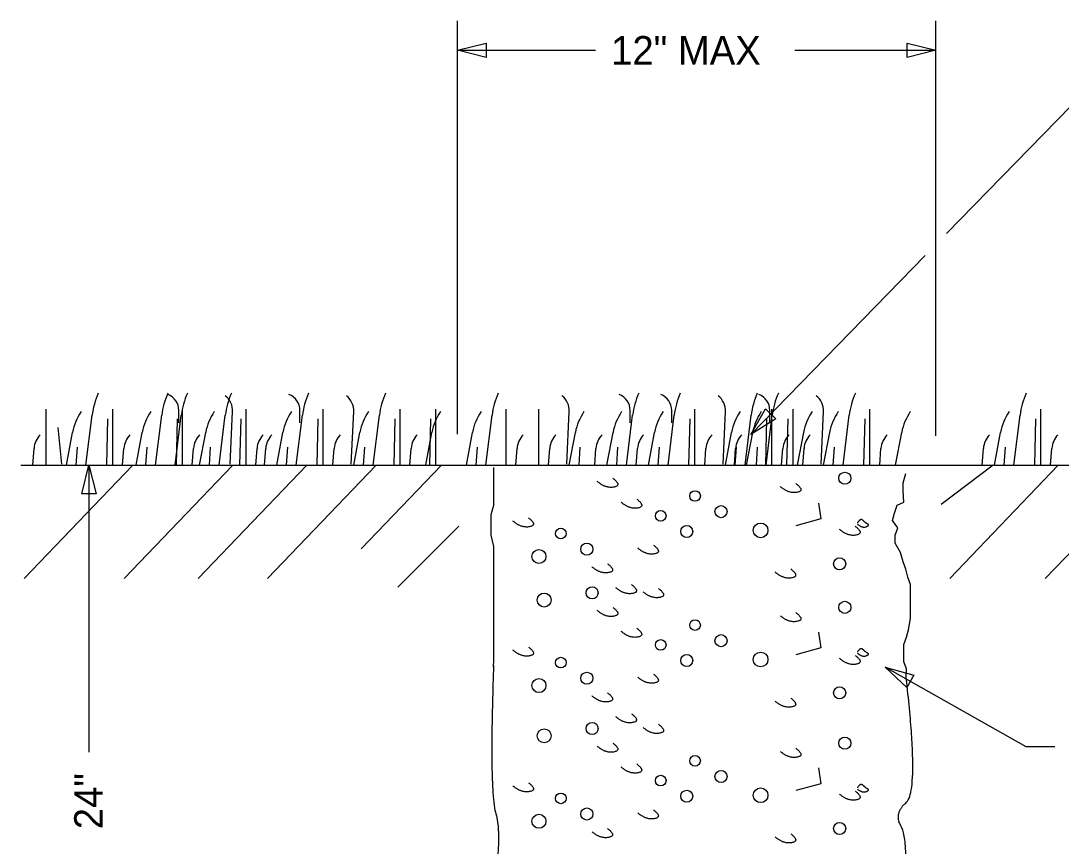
# Model space of a CAD drawing. Extents: x 10111 to 10157.2, y 10072.4 to 10116.1.
# Drawn here: x 10110.98 to 10135.23, y 10096.92 to 10116.14 of the extents above; entities that cross this region are included whole.
import ezdxf

# ---------------------------------------------------------------- set-up
doc = ezdxf.new("R2010")
doc.units = 0
for name, color, linetype in [('G-ANNO-TEXT', 7, 'Continuous'), ('G-DETL-LINE', 7, 'Continuous'), ('G-DETL-PATT', 7, 'Continuous')]:
    doc.layers.add(name, color=color, linetype=linetype)

msp = doc.modelspace()

# ---------------------------------------------------------------- linework, layer by layer
at = {"layer": 'G-ANNO-TEXT'}
for p, q in [((10121.155, 10106.519), (10121.155, 10116.144)), ((10132.304, 10106.479), (10132.304, 10116.144)), ((10121.155, 10115.459), (10124.375, 10115.459)), ((10129.02, 10115.459), (10132.304, 10115.459)), ((10135.967, 10114.69), (10132.554, 10111.19)), ((10132.054, 10110.677), (10127.992, 10106.511)), ((10112.564, 10105.794), (10112.564, 10099.107)), ((10134.41, 10099.234), (10131.128, 10101.086)), ((10135.076, 10099.234), (10134.41, 10099.234))]:
    msp.add_line(p, q, dxfattribs=at)
for points in [[(10121.822, 10115.292), (10121.155, 10115.459), (10121.822, 10115.626)], [(10131.637, 10115.626), (10132.304, 10115.459), (10131.637, 10115.292)], [(10128.577, 10106.872), (10127.992, 10106.511), (10128.339, 10107.105)], [(10112.398, 10105.127), (10112.564, 10105.794), (10112.731, 10105.127)], [(10131.627, 10100.613), (10131.128, 10101.086), (10131.79, 10100.904)]]:
    msp.add_lwpolyline(points, close=True, dxfattribs=at)
at = {"layer": 'G-DETL-LINE'}
msp.add_line((10110.977, 10105.793), (10143.768, 10105.793), dxfattribs=at)
for points in [[(10121.995, 10101.091), (10122.002, 10101.262), (10122.002, 10101.448), (10122.002, 10101.618), (10122.002, 10101.789), (10122.002, 10102.052), (10122.002, 10102.238), (10122.002, 10102.455), (10122.002, 10102.672), (10122.002, 10102.936), (10122.002, 10103.199), (10122.002, 10103.416), (10122.002, 10103.633), (10122.002, 10103.897), (10121.94, 10104.16), (10121.94, 10104.424), (10121.94, 10104.641), (10122.002, 10104.858), (10122.002, 10105.075), (10122.002, 10105.338), (10122.002, 10105.524), (10122.002, 10105.741)], [(10131.617, 10100.825), (10131.622, 10101.045), (10131.56, 10101.215), (10131.56, 10101.432), (10131.56, 10101.618), (10131.622, 10101.789), (10131.669, 10101.959), (10131.715, 10102.223), (10131.715, 10102.44), (10131.715, 10102.626), (10131.715, 10102.843), (10131.715, 10103.013), (10131.653, 10103.184), (10131.607, 10103.37), (10131.545, 10103.54), (10131.483, 10103.757), (10131.359, 10103.974), (10131.359, 10104.16), (10131.421, 10104.331), (10131.297, 10104.501), (10131.343, 10104.672), (10131.405, 10104.858), (10131.56, 10104.935), (10131.545, 10105.199), (10131.545, 10105.385), (10131.607, 10105.602)]]:
    msp.add_lwpolyline(points, dxfattribs=at)
msp.add_open_spline([(10121.996, 10101.13), (10121.895, 10098.19), (10122.199, 10097.176), (10121.794, 10094.642), (10122.401, 10092.412), (10122.3, 10091.095), (10122.806, 10090.284), (10122.098, 10088.865), (10122.604, 10085.52), (10125.541, 10086.027), (10127.768, 10085.115), (10129.49, 10086.027), (10130.908, 10086.331), (10131.718, 10088.358), (10131.212, 10092.514), (10131.718, 10096.973), (10131.313, 10097.683), (10131.92, 10098.19), (10131.617, 10100.825)], degree=2, dxfattribs=at)
at = {"layer": 'G-DETL-PATT'}
for p, q in [((10113.591, 10105.791), (10111.059, 10103.156)), ((10115.92, 10105.791), (10113.389, 10103.156)), ((10117.642, 10105.791), (10115.11, 10103.156)), ((10119.262, 10105.791), (10116.73, 10103.156)), ((10120.781, 10105.791), (10118.912, 10103.846)), ((10133.642, 10105.791), (10132.427, 10104.879)), ((10135.161, 10105.791), (10132.629, 10103.156)), ((10137.389, 10105.791), (10134.857, 10103.156)), ((10129.571, 10104.91), (10129.624, 10104.542)), ((10121.186, 10104.372), (10119.768, 10102.953)), ((10129.624, 10104.542), (10129.045, 10104.383)), ((10129.571, 10101.903), (10129.624, 10101.535)), ((10129.624, 10101.535), (10129.045, 10101.377)), ((10129.571, 10098.741), (10129.624, 10098.373)), ((10129.624, 10098.373), (10129.045, 10098.215))]:
    msp.add_line(p, q, dxfattribs=at)
for points in [[(10111.57, 10105.793), (10111.57, 10107.097)], [(10113.123, 10105.793), (10113.123, 10107.097)], [(10114.661, 10106.783), (10114.661, 10107.068)], [(10114.746, 10105.793), (10114.746, 10107.097)], [(10115.857, 10105.814), (10115.914, 10107.04)], [(10116.227, 10105.793), (10116.227, 10107.097)], [(10117.484, 10106.783), (10117.484, 10107.068)], [(10118.025, 10105.793), (10118.025, 10107.097)], [(10118.68, 10105.814), (10118.737, 10107.04)], [(10119.819, 10105.793), (10119.819, 10107.097)], [(10120.651, 10105.793), (10120.651, 10107.097)], [(10122.289, 10105.793), (10122.289, 10107.097)], [(10123.05, 10105.793), (10123.05, 10107.097)], [(10123.705, 10105.814), (10123.762, 10107.04)], [(10125.181, 10106.783), (10125.181, 10107.068)], [(10126.149, 10106.783), (10126.149, 10107.068)], [(10126.69, 10105.793), (10126.69, 10107.097)], [(10127.345, 10105.814), (10127.402, 10107.04)], [(10128.436, 10106.783), (10128.436, 10107.068)], [(10128.484, 10105.793), (10128.484, 10107.097)], [(10128.977, 10105.793), (10128.977, 10107.097)], [(10129.632, 10105.814), (10129.689, 10107.04)], [(10130.771, 10105.793), (10130.771, 10107.097)], [(10134.753, 10105.793), (10134.753, 10107.097)], [(10112.496, 10105.793), (10112.639, 10106.954)], [(10112.98, 10105.793), (10113.009, 10106.869)], [(10114.12, 10105.793), (10114.262, 10106.954)], [(10114.575, 10105.793), (10114.718, 10106.954)], [(10114.604, 10105.793), (10114.632, 10106.869)], [(10115.6, 10105.793), (10115.743, 10106.954)], [(10116.085, 10105.793), (10116.113, 10106.869)], [(10117.398, 10105.793), (10117.541, 10106.954)], [(10117.883, 10105.793), (10117.911, 10106.869)], [(10119.193, 10105.793), (10119.335, 10106.954)], [(10119.677, 10105.793), (10119.705, 10106.869)], [(10120.509, 10105.793), (10120.537, 10106.869)], [(10121.819, 10105.793), (10121.961, 10106.954)], [(10125.095, 10105.793), (10125.238, 10106.954)], [(10126.064, 10105.793), (10126.206, 10106.954)], [(10126.548, 10105.793), (10126.576, 10106.869)], [(10127.858, 10105.793), (10128, 10106.954)], [(10128.342, 10105.793), (10128.37, 10106.869)], [(10128.35, 10105.793), (10128.493, 10106.954)], [(10128.834, 10105.793), (10128.863, 10106.869)], [(10130.144, 10105.793), (10130.287, 10106.954)], [(10130.628, 10105.793), (10130.657, 10106.869)], [(10134.127, 10105.793), (10134.269, 10106.954)], [(10134.611, 10105.793), (10134.639, 10106.869)], [(10111.841, 10106.669), (10111.927, 10105.814)], [(10112.041, 10105.793), (10112.183, 10106.555)], [(10113.664, 10105.793), (10113.806, 10106.555)], [(10115.145, 10105.793), (10115.287, 10106.555)], [(10116.943, 10105.793), (10117.085, 10106.555)], [(10118.737, 10105.793), (10118.879, 10106.555)], [(10120.417, 10105.793), (10120.56, 10106.555)], [(10121.363, 10105.793), (10121.505, 10106.555)], [(10123.762, 10105.793), (10123.904, 10106.555)], [(10124.64, 10105.793), (10124.782, 10106.555)], [(10125.608, 10105.793), (10125.75, 10106.555)], [(10127.402, 10105.793), (10127.544, 10106.555)], [(10127.894, 10105.793), (10128.037, 10106.555)], [(10129.082, 10105.793), (10129.225, 10106.555)], [(10129.689, 10105.793), (10129.831, 10106.555)], [(10131.369, 10105.793), (10131.511, 10106.555)], [(10133.671, 10105.793), (10133.814, 10106.555)], [(10111.257, 10105.793), (10111.285, 10106.185)], [(10112.268, 10105.793), (10112.297, 10106.213)], [(10113.351, 10105.793), (10113.379, 10106.185)], [(10113.892, 10105.793), (10113.92, 10106.213)], [(10114.974, 10105.793), (10115.002, 10106.185)], [(10115.373, 10105.793), (10115.401, 10106.213)], [(10116.455, 10105.793), (10116.483, 10106.185)], [(10116.658, 10105.793), (10116.687, 10106.185)], [(10117.171, 10105.793), (10117.199, 10106.213)], [(10118.253, 10105.793), (10118.281, 10106.185)], [(10118.965, 10105.793), (10118.993, 10106.213)], [(10120.047, 10105.793), (10120.075, 10106.185)], [(10121.591, 10105.793), (10121.619, 10106.213)], [(10122.517, 10105.793), (10122.545, 10106.185)], [(10123.278, 10105.793), (10123.306, 10106.185)], [(10123.99, 10105.793), (10124.018, 10106.213)], [(10124.355, 10105.793), (10124.383, 10106.185)], [(10124.868, 10105.793), (10124.896, 10106.213)], [(10125.323, 10105.793), (10125.352, 10106.185)], [(10125.836, 10105.793), (10125.864, 10106.213)], [(10126.918, 10105.793), (10126.946, 10106.185)], [(10127.61, 10105.793), (10127.638, 10106.185)], [(10127.63, 10105.793), (10127.658, 10106.213)], [(10128.122, 10105.793), (10128.151, 10106.213)], [(10128.712, 10105.793), (10128.741, 10106.185)], [(10129.204, 10105.793), (10129.233, 10106.185)], [(10129.916, 10105.793), (10129.945, 10106.213)], [(10130.999, 10105.793), (10131.027, 10106.185)], [(10133.386, 10105.793), (10133.415, 10106.185)], [(10133.899, 10105.793), (10133.927, 10106.213)], [(10134.981, 10105.793), (10135.01, 10106.185)]]:
    msp.add_lwpolyline(points, dxfattribs=at)
for centre, radius in [((10130.185, 10105.488), 0.141), ((10126.693, 10105.075), 0.124), ((10127.299, 10104.711), 0.141), ((10125.892, 10104.613), 0.124), ((10126.499, 10104.249), 0.141), ((10128.22, 10104.273), 0.172), ((10123.565, 10104.2), 0.124), ((10124.171, 10103.836), 0.141), ((10123.055, 10103.666), 0.163), ((10130.063, 10103.496), 0.141), ((10124.293, 10102.82), 0.141), ((10123.177, 10102.651), 0.163), ((10130.185, 10102.481), 0.141), ((10126.693, 10102.068), 0.124), ((10125.892, 10101.606), 0.124), ((10127.299, 10101.704), 0.141), ((10128.22, 10101.266), 0.172), ((10123.565, 10101.193), 0.124), ((10126.499, 10101.242), 0.141), ((10124.171, 10100.829), 0.141), ((10123.055, 10100.659), 0.163), ((10130.063, 10100.49), 0.141), ((10124.293, 10099.658), 0.141), ((10123.177, 10099.489), 0.163), ((10130.185, 10099.319), 0.141), ((10126.693, 10098.906), 0.124), ((10125.892, 10098.444), 0.124), ((10127.299, 10098.542), 0.141), ((10128.22, 10098.104), 0.172), ((10123.565, 10098.031), 0.124), ((10126.499, 10098.08), 0.141), ((10124.171, 10097.667), 0.141), ((10123.055, 10097.497), 0.163), ((10130.063, 10097.328), 0.141)]:
    msp.add_circle(centre, radius, dxfattribs=at)
for centre, radius, start, end in [((10114.422, 10106.736), 1.796, 155.9651, 173.0105), ((10116.045, 10106.736), 1.796, 155.9651, 173.0105), ((10114.265, 10107.068), 0.396, 0, 69.3471), ((10116.501, 10106.736), 1.796, 155.9651, 173.0105), ((10117.526, 10106.736), 1.796, 155.9651, 173.0105), ((10115.471, 10107.06), 0.443, 357.3391, 52.176), ((10117.088, 10107.068), 0.396, 0, 69.3471), ((10119.324, 10106.736), 1.796, 155.9651, 173.0105), ((10118.294, 10107.06), 0.443, 357.3391, 52.176), ((10121.118, 10106.736), 1.796, 155.9651, 173.0105), ((10123.744, 10106.736), 1.796, 155.9651, 173.0105), ((10123.319, 10107.06), 0.443, 357.3391, 52.176), ((10124.785, 10107.068), 0.396, 0, 69.3471), ((10127.021, 10106.736), 1.796, 155.9651, 173.0105), ((10125.753, 10107.068), 0.396, 0, 69.3471), ((10127.989, 10106.736), 1.796, 155.9651, 173.0105), ((10126.959, 10107.06), 0.443, 357.3391, 52.176), ((10129.783, 10106.736), 1.796, 155.9651, 173.0105), ((10128.04, 10107.068), 0.396, 0, 69.3471), ((10130.275, 10106.736), 1.796, 155.9651, 173.0105), ((10129.246, 10107.06), 0.443, 357.3391, 52.176), ((10132.07, 10106.736), 1.796, 155.9651, 173.0105), ((10136.052, 10106.736), 1.796, 155.9651, 173.0105), ((10113.444, 10106.32), 1.283, 145.8509, 169.4213), ((10115.067, 10106.32), 1.283, 145.8509, 169.4213), ((10116.548, 10106.32), 1.283, 145.8509, 169.4213), ((10118.346, 10106.32), 1.283, 145.8509, 169.4213), ((10120.14, 10106.32), 1.283, 145.8509, 169.4213), ((10121.82, 10106.32), 1.283, 145.8509, 169.4213), ((10122.766, 10106.32), 1.283, 145.8509, 169.4213), ((10125.165, 10106.32), 1.283, 145.8509, 169.4213), ((10126.043, 10106.32), 1.283, 145.8509, 169.4213), ((10127.011, 10106.32), 1.283, 145.8509, 169.4213), ((10128.805, 10106.32), 1.283, 145.8509, 169.4213), ((10129.298, 10106.32), 1.283, 145.8509, 169.4213), ((10130.485, 10106.32), 1.283, 145.8509, 169.4213), ((10131.092, 10106.32), 1.283, 145.8509, 169.4213), ((10132.772, 10106.32), 1.283, 145.8509, 169.4213), ((10135.074, 10106.32), 1.283, 145.8509, 169.4213), ((10111.781, 10106.149), 0.497, 135.303, 175.8439), ((10113.875, 10106.149), 0.497, 135.303, 175.8439), ((10115.498, 10106.149), 0.497, 135.303, 175.8439), ((10116.979, 10106.149), 0.497, 135.303, 175.8439), ((10117.182, 10106.149), 0.497, 135.303, 175.8439), ((10118.777, 10106.149), 0.497, 135.303, 175.8439), ((10120.571, 10106.149), 0.497, 135.303, 175.8439), ((10123.041, 10106.149), 0.497, 135.303, 175.8439), ((10123.802, 10106.149), 0.497, 135.303, 175.8439), ((10124.879, 10106.149), 0.497, 135.303, 175.8439), ((10125.847, 10106.149), 0.497, 135.303, 175.8439), ((10127.442, 10106.149), 0.497, 135.303, 175.8439), ((10128.134, 10106.149), 0.497, 135.303, 175.8439), ((10129.236, 10106.149), 0.497, 135.303, 175.8439), ((10129.729, 10106.149), 0.497, 135.303, 175.8439), ((10131.523, 10106.149), 0.497, 135.303, 175.8439), ((10133.91, 10106.149), 0.497, 135.303, 175.8439), ((10135.505, 10106.149), 0.497, 135.303, 175.8439)]:
    msp.add_arc(centre, radius, start, end, dxfattribs=at)
for points in [[(10124.778, 10105.488), (10124.996, 10105.318), (10124.608, 10105.245), (10124.414, 10105.415)], [(10129.045, 10105.366), (10129.264, 10105.196), (10128.876, 10105.124), (10128.682, 10105.293)], [(10125.335, 10105.002), (10125.554, 10104.832), (10125.166, 10104.759), (10124.972, 10104.929)], [(10122.813, 10104.564), (10123.031, 10104.395), (10122.643, 10104.322), (10122.449, 10104.492)], [(10130.427, 10104.37), (10130.645, 10104.2), (10130.257, 10104.128), (10130.063, 10104.297)], [(10130.476, 10104.42), (10130.597, 10104.323), (10130.767, 10104.395), (10130.67, 10104.444), (10130.549, 10104.565), (10130.476, 10104.444)], [(10125.723, 10103.933), (10125.941, 10103.763), (10125.553, 10103.691), (10125.359, 10103.861)], [(10124.656, 10103.496), (10124.874, 10103.327), (10124.486, 10103.254), (10124.292, 10103.424)], [(10128.923, 10103.375), (10129.142, 10103.205), (10128.754, 10103.132), (10128.56, 10103.302)], [(10125.213, 10103.011), (10125.432, 10102.841), (10125.044, 10102.768), (10124.85, 10102.938)], [(10125.844, 10102.918), (10126.063, 10102.748), (10125.675, 10102.675), (10125.481, 10102.845)], [(10124.778, 10102.481), (10124.996, 10102.311), (10124.608, 10102.238), (10124.414, 10102.408)], [(10129.045, 10102.359), (10129.264, 10102.189), (10128.876, 10102.117), (10128.682, 10102.286)], [(10125.335, 10101.995), (10125.554, 10101.825), (10125.166, 10101.752), (10124.972, 10101.922)], [(10122.813, 10101.557), (10123.031, 10101.388), (10122.643, 10101.315), (10122.449, 10101.485)], [(10130.476, 10101.413), (10130.597, 10101.316), (10130.767, 10101.388), (10130.67, 10101.437), (10130.549, 10101.558), (10130.476, 10101.437)], [(10130.427, 10101.363), (10130.645, 10101.193), (10130.257, 10101.121), (10130.063, 10101.29)], [(10125.723, 10100.926), (10125.941, 10100.756), (10125.553, 10100.684), (10125.359, 10100.854)], [(10124.656, 10100.49), (10124.874, 10100.32), (10124.486, 10100.247), (10124.292, 10100.417)], [(10128.923, 10100.368), (10129.142, 10100.198), (10128.754, 10100.125), (10128.56, 10100.295)], [(10125.213, 10100.004), (10125.432, 10099.834), (10125.044, 10099.761), (10124.85, 10099.931)], [(10125.844, 10099.756), (10126.063, 10099.586), (10125.675, 10099.513), (10125.481, 10099.683)], [(10124.778, 10099.319), (10124.996, 10099.149), (10124.608, 10099.076), (10124.414, 10099.246)], [(10129.045, 10099.197), (10129.264, 10099.027), (10128.876, 10098.955), (10128.682, 10099.124)], [(10125.335, 10098.833), (10125.554, 10098.663), (10125.166, 10098.59), (10124.972, 10098.76)], [(10122.813, 10098.395), (10123.031, 10098.226), (10122.643, 10098.153), (10122.449, 10098.323)], [(10130.476, 10098.251), (10130.597, 10098.154), (10130.767, 10098.226), (10130.67, 10098.275), (10130.549, 10098.396), (10130.476, 10098.275)], [(10130.427, 10098.201), (10130.645, 10098.031), (10130.257, 10097.959), (10130.063, 10098.129)], [(10125.723, 10097.764), (10125.941, 10097.595), (10125.553, 10097.522), (10125.359, 10097.692)], [(10124.656, 10097.328), (10124.874, 10097.158), (10124.486, 10097.085), (10124.292, 10097.255)], [(10128.923, 10097.206), (10129.142, 10097.036), (10128.754, 10096.963), (10128.56, 10097.133)]]:
    msp.add_open_spline(points, degree=2, dxfattribs=at)

# ---------------------------------------------------------------- texts
at = {"layer": 'G-ANNO-TEXT'}
msp.add_text('12" MAX', height=0.6667, dxfattribs=at).set_placement((10124.737, 10115.123))
msp.add_text('24"', height=0.6667, rotation=90, dxfattribs=at).set_placement((10112.888, 10097.312))

doc.saveas('drawing.dxf')
